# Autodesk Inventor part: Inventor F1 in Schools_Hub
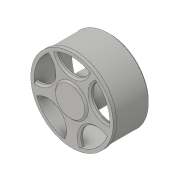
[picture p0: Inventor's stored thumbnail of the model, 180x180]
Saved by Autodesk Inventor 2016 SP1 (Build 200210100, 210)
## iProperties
Created: 2015-12
Part Number: Inventor F1 in Schools_Hub
Material: Generic
Document SubType Name: Modeling
Designer: Autodesk Inc.
Density: 1 g/cm^3
Appearance: Default
Author: Autodesk Inc
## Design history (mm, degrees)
feature "Body1"
body "Solid1"
